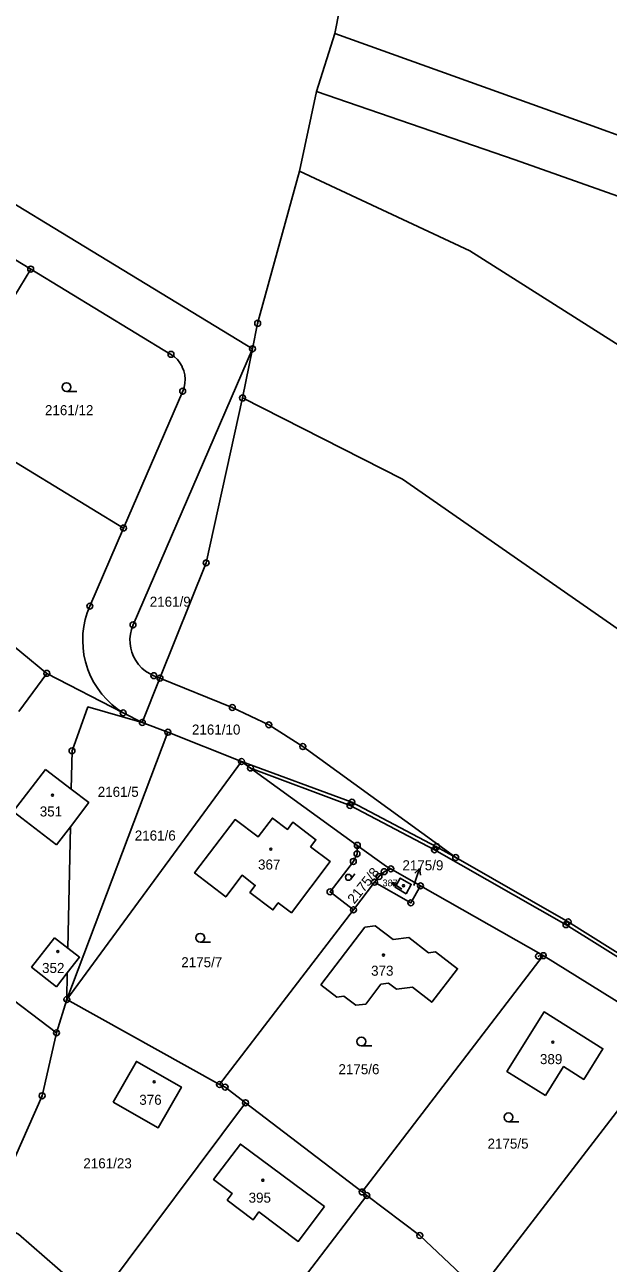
# Model space of a CAD drawing. Extents: x -725728 to -720881, y -1068679 to -1063504.
# Drawn here: x -721484.1 to -721385.1, y -1066663.8 to -1066453.8 of the extents above; entities that cross this region are included whole.
import ezdxf

# ---------------------------------------------------------------- set-up
doc = ezdxf.new("R2010")
doc.units = 0
for name, color, linetype in [('Hranice parcel', 7, 'Continuous'), ('Parcelní čísla', 7, 'Continuous'), ('Pop  PČ popisy', 7, 'Continuous'), ('Značky bodu BP', 7, 'Continuous'), ('Značky budov', 7, 'Continuous'), ('Značky kultur', 7, 'Continuous')]:
    doc.layers.add(name, color=color, linetype=linetype)

msp = doc.modelspace()

# ---------------------------------------------------------------- linework, layer by layer
at = {"layer": 'Hranice parcel'}
for p, q in [((-721434.62, -1066465.11), (-721431.52, -1066455.27)), ((-721437.52, -1066478.62), (-721434.62, -1066465.11)), ((-721500.53, -1066484.64), (-721483.09, -1066495.24)), ((-721498.34, -1066520.32), (-721483.09, -1066495.24)), ((-721483.09, -1066495.24), (-721459.3, -1066509.71)), ((-721445.47, -1066508.75), (-721465.73, -1066555.59)), ((-721447.15, -1066517.1), (-721445.47, -1066508.75)), ((-721457.31, -1066515.96), (-721467.34, -1066539.16)), ((-721453.33, -1066545.06), (-721447.15, -1066517.1)), ((-721467.34, -1066539.16), (-721498.34, -1066520.32)), ((-721467.34, -1066539.16), (-721473.07, -1066552.41)), ((-721461.16, -1066564.63), (-721453.33, -1066545.06)), ((-721499.96, -1066547.69), (-721480.36, -1066563.81)), ((-721480.36, -1066563.81), (-721485.1, -1066570.29)), ((-721480.36, -1066563.81), (-721467.4, -1066570.5)), ((-721461.16, -1066564.63), (-721464.16, -1066572.13)), ((-721462.21, -1066564.2), (-721461.16, -1066564.63)), ((-721467.4, -1066570.5), (-721464.16, -1066572.13)), ((-721464.16, -1066572.13), (-721459.81, -1066573.8)), ((-721476.97, -1066619.11), (-721459.81, -1066573.8)), ((-721459.81, -1066573.8), (-721447.33, -1066578.75)), ((-721476.97, -1066619.11), (-721447.33, -1066578.75)), ((-721445.8, -1066579.86), (-721447.33, -1066578.75)), ((-721447.33, -1066578.75), (-721428.6, -1066585.67)), ((-721427.69, -1066592.98), (-721445.8, -1066579.86)), ((-721480.57, -1066580.11), (-721476.22, -1066583.44)), ((-721428.6, -1066585.67), (-721414.24, -1066593.2)), ((-721476.35, -1066589.81), (-721478.7, -1066592.87)), ((-721476.35, -1066589.81), (-721476.79, -1066610.42)), ((-721414.24, -1066593.2), (-721411, -1066595.05)), ((-721416.97, -1066599.84), (-721422.01, -1066596.97)), ((-721424.76, -1066599.21), (-721428.35, -1066603.9)), ((-721396.15, -1066611.68), (-721416.97, -1066599.84)), ((-721508.7, -1066602.07), (-721478.72, -1066624.77)), ((-721428.35, -1066603.9), (-721451.07, -1066633.53)), ((-721479.07, -1066608.65), (-721476.79, -1066610.42)), ((-721396.15, -1066611.68), (-721426.87, -1066651.76)), ((-721373.98, -1066625.5), (-721396.15, -1066611.68)), ((-721476.88, -1066614.6), (-721478.71, -1066616.95)), ((-721476.88, -1066614.6), (-721476.97, -1066619.11)), ((-721476.97, -1066619.11), (-721478.72, -1066624.77)), ((-721451.07, -1066633.53), (-721476.97, -1066619.11)), ((-721373.98, -1066625.5), (-721407.06, -1066668.61)), ((-721471.92, -1066670.45), (-721446.66, -1066636.63)), ((-721426.87, -1066651.76), (-721446.66, -1066636.63)), ((-721452.81, -1066687.35), (-721426.08, -1066652.36)), ((-721426.08, -1066652.36), (-721426.87, -1066651.76))]:
    msp.add_line(p, q, dxfattribs=at)
for points in [[(-721431.52, -1066455.27), (-721424.48, -1066419.67), (-721421.78, -1066392.38)], [(-721592.64, -1066419.28), (-721519.06, -1066464.02), (-721445.47, -1066508.75)], [(-721230.65, -1066526.44), (-721277.41, -1066511.11), (-721331.05, -1066491.51), (-721388.47, -1066470.7), (-721431.52, -1066455.27)], [(-721434.62, -1066465.11), (-721400.9, -1066476.72), (-721289.85, -1066516.02), (-721253.91, -1066529.25), (-721228.92, -1066541.28)], [(-721445.47, -1066508.75), (-721444.6, -1066504.45), (-721437.52, -1066478.62)], [(-721437.52, -1066478.62), (-721408.58, -1066492.16), (-721301.3, -1066560.17), (-721252.76, -1066592.17), (-721191.02, -1066626.24)], [(-721459.3, -1066509.71), (-721458.72, -1066510.12), (-721458.21, -1066510.6), (-721457.77, -1066511.15), (-721457.41, -1066511.76), (-721457.37, -1066511.85), (-721457.11, -1066512.51), (-721456.96, -1066513.2), (-721456.9, -1066513.9), (-721456.94, -1066514.6), (-721457.07, -1066515.3), (-721457.31, -1066515.96)], [(-721447.15, -1066517.1), (-721420.03, -1066530.86), (-721379.52, -1066559), (-721269.58, -1066620.68), (-721222.77, -1066645.27)], [(-721473.07, -1066552.41), (-721473.5, -1066553.53), (-721473.84, -1066554.69), (-721474.08, -1066555.87), (-721474.22, -1066557.07), (-721474.26, -1066558.27), (-721474.21, -1066559.47), (-721474.05, -1066560.67), (-721473.79, -1066561.84), (-721473.74, -1066562.02), (-721473.38, -1066563.17), (-721472.92, -1066564.28), (-721472.36, -1066565.35), (-721471.72, -1066566.37), (-721471, -1066567.33), (-721470.2, -1066568.24), (-721469.33, -1066569.07), (-721468.4, -1066569.82), (-721467.4, -1066570.5)], [(-721465.73, -1066555.59), (-721466, -1066556.35), (-721466.18, -1066557.14), (-721466.26, -1066557.94), (-721466.24, -1066558.74), (-721466.12, -1066559.54), (-721465.94, -1066560.2), (-721465.65, -1066560.95), (-721465.26, -1066561.65), (-721464.78, -1066562.31), (-721464.23, -1066562.9), (-721463.61, -1066563.41), (-721462.94, -1066563.85), (-721462.21, -1066564.2)], [(-721411, -1066595.05), (-721436.92, -1066576.23), (-721442.7, -1066572.55), (-721448.89, -1066569.59), (-721461.16, -1066564.63)], [(-721464.16, -1066572.13), (-721473.37, -1066569.51), (-721476.08, -1066576.96), (-721476.22, -1066583.44)], [(-721293.92, -1066677.55), (-721362.35, -1066625.09), (-721392.29, -1066606.43), (-721414.6, -1066593.72), (-721428.93, -1066586.2), (-721445.8, -1066579.86)], [(-721478.7, -1066592.87), (-721486.07, -1066587.25), (-721480.57, -1066580.11)], [(-721476.22, -1066583.44), (-721473.23, -1066585.73), (-721476.35, -1066589.81)], [(-721435.63, -1066593.22), (-721432.27, -1066595.72), (-721438.88, -1066604.4), (-721441.09, -1066602.72), (-721442.01, -1066603.92), (-721445.91, -1066600.95), (-721445, -1066599.76), (-721447.23, -1066598.06), (-721450.01, -1066601.73), (-721455.3, -1066597.66), (-721448.42, -1066588.62), (-721444.48, -1066591.52), (-721442.08, -1066588.35), (-721439.53, -1066590.26), (-721438.63, -1066589.06), (-721434.71, -1066592.02), (-721435.63, -1066593.22)], [(-721428.35, -1066603.9), (-721432.32, -1066600.86), (-721428.36, -1066595.7), (-721427.74, -1066594.41), (-721427.69, -1066592.98)], [(-721422.01, -1066596.97), (-721422.73, -1066596.57), (-721427.69, -1066592.98)], [(-721411, -1066595.05), (-721391.94, -1066605.94), (-721362.07, -1066624.68), (-721293.39, -1066677.33)], [(-721424.76, -1066599.21), (-721424.02, -1066598.27), (-721423.13, -1066597.44), (-721422.01, -1066596.97)], [(-721419.39, -1066601.18), (-721421.29, -1066600.09), (-721420.4, -1066598.53), (-721418.53, -1066599.61), (-721419.39, -1066601.18)], [(-721416.97, -1066599.84), (-721418.6, -1066602.72), (-721424.76, -1066599.21)], [(-721433.88, -1066616.63), (-721426.39, -1066606.87), (-721424.68, -1066606.64), (-721421.63, -1066608.95), (-721418.96, -1066608.61), (-721415.6, -1066611.19), (-721414.42, -1066611.05), (-721410.69, -1066613.91), (-721415.06, -1066619.59), (-721418.35, -1066617.03), (-721421.06, -1066617.39), (-721422.42, -1066616.36), (-721423.68, -1066616.53), (-721426.27, -1066619.92), (-721427.96, -1066620.1), (-721429.95, -1066618.56), (-721431.17, -1066618.72), (-721433.88, -1066616.63)], [(-721478.71, -1066616.95), (-721482.94, -1066613.62), (-721479.07, -1066608.65)], [(-721476.79, -1066610.42), (-721474.81, -1066611.96), (-721476.88, -1066614.6)], [(-721395.76, -1066635.4), (-721402.31, -1066631.31), (-721396, -1066621.22), (-721386.02, -1066627.47), (-721389.28, -1066632.66), (-721392.71, -1066630.51), (-721395.76, -1066635.4)], [(-721478.72, -1066624.77), (-721481.16, -1066635.44), (-721490.49, -1066656.42)], [(-721469.08, -1066636.53), (-721465.15, -1066629.61), (-721457.53, -1066633.96), (-721461.46, -1066640.88), (-721469.08, -1066636.53)], [(-721446.66, -1066636.63), (-721450.11, -1066633.99), (-721451.07, -1066633.53)], [(-721433.28, -1066654.24), (-721447.51, -1066643.64), (-721452.06, -1066649.66), (-721448.9, -1066652.03), (-721449.76, -1066653.13), (-721445.34, -1066656.46), (-721444.37, -1066655.15), (-721437.7, -1066660.14), (-721433.28, -1066654.24)], [(-721407.06, -1066668.61), (-721417.1, -1066659.15), (-721426.08, -1066652.36)], [(-721490.49, -1066656.42), (-721485.18, -1066658.89), (-721471.92, -1066670.45)]]:
    msp.add_lwpolyline(points, dxfattribs=at)
at = {"layer": 'Pop  PČ popisy'}
for p, q in [((-721418.08, -1066599.76), (-721417.15, -1066596.91)), ((-721417.15, -1066596.91), (-721417.94, -1066597.7)), ((-721417.15, -1066596.91), (-721416.99, -1066598.01)), ((-721420.14, -1066600.41), (-721421.79, -1066599.26)), ((-721421.79, -1066599.26), (-721421.05, -1066599.37)), ((-721421.79, -1066599.26), (-721421.43, -1066599.92))]:
    msp.add_line(p, q, dxfattribs=at)
at = {"layer": 'Značky bodu BP'}
for centre, radius in [((-721483.09, -1066495.24), 0.5), ((-721483.09, -1066495.24), 0.0303), ((-721444.6, -1066504.45), 0.5), ((-721444.6, -1066504.45), 0.0303), ((-721445.47, -1066508.75), 0.5), ((-721459.3, -1066509.71), 0.5), ((-721459.3, -1066509.71), 0.0303), ((-721445.47, -1066508.75), 0.0303), ((-721457.31, -1066515.96), 0.5), ((-721457.31, -1066515.96), 0.0303), ((-721447.15, -1066517.1), 0.5), ((-721447.15, -1066517.1), 0.0303), ((-721467.34, -1066539.16), 0.5), ((-721467.34, -1066539.16), 0.0303), ((-721453.33, -1066545.06), 0.5), ((-721453.33, -1066545.06), 0.0303), ((-721473.07, -1066552.41), 0.5), ((-721473.07, -1066552.41), 0.0303), ((-721465.73, -1066555.59), 0.5), ((-721465.73, -1066555.59), 0.0303), ((-721480.36, -1066563.81), 0.5), ((-721480.36, -1066563.81), 0.0303), ((-721462.21, -1066564.2), 0.5), ((-721462.21, -1066564.2), 0.0303), ((-721461.16, -1066564.63), 0.5), ((-721461.16, -1066564.63), 0.0303), ((-721448.89, -1066569.59), 0.5), ((-721467.4, -1066570.5), 0.5), ((-721467.4, -1066570.5), 0.0303), ((-721448.89, -1066569.59), 0.0303), ((-721464.16, -1066572.13), 0.5), ((-721464.16, -1066572.13), 0.0303), ((-721459.81, -1066573.8), 0.5), ((-721442.7, -1066572.55), 0.5), ((-721442.7, -1066572.55), 0.0303), ((-721459.81, -1066573.8), 0.0303), ((-721476.08, -1066576.96), 0.5), ((-721476.08, -1066576.96), 0.0303), ((-721436.92, -1066576.23), 0.5), ((-721436.92, -1066576.23), 0.0303), ((-721447.33, -1066578.75), 0.5), ((-721447.33, -1066578.75), 0.0303), ((-721445.8, -1066579.86), 0.5), ((-721445.8, -1066579.86), 0.0303), ((-721428.93, -1066586.2), 0.5), ((-721428.6, -1066585.67), 0.5), ((-721428.93, -1066586.2), 0.0303), ((-721428.6, -1066585.67), 0.0303), ((-721427.69, -1066592.98), 0.5), ((-721427.74, -1066594.41), 0.5), ((-721427.74, -1066594.41), 0.0303), ((-721427.69, -1066592.98), 0.0303), ((-721414.6, -1066593.72), 0.5), ((-721414.24, -1066593.2), 0.5), ((-721414.6, -1066593.72), 0.0303), ((-721414.24, -1066593.2), 0.0303), ((-721411, -1066595.05), 0.5), ((-721428.36, -1066595.7), 0.5), ((-721428.36, -1066595.7), 0.0303), ((-721422.01, -1066596.97), 0.5), ((-721411, -1066595.05), 0.0303), ((-721424.76, -1066599.21), 0.5), ((-721424.02, -1066598.27), 0.5), ((-721424.02, -1066598.27), 0.0303), ((-721423.13, -1066597.44), 0.5), ((-721423.13, -1066597.44), 0.0303), ((-721422.01, -1066596.97), 0.0303), ((-721432.32, -1066600.86), 0.5), ((-721432.32, -1066600.86), 0.0303), ((-721424.76, -1066599.21), 0.0303), ((-721416.97, -1066599.84), 0.5), ((-721416.97, -1066599.84), 0.0303), ((-721418.6, -1066602.72), 0.5), ((-721418.6, -1066602.72), 0.0303), ((-721428.35, -1066603.9), 0.5), ((-721428.35, -1066603.9), 0.0303), ((-721392.29, -1066606.43), 0.5), ((-721391.94, -1066605.94), 0.5), ((-721392.29, -1066606.43), 0.0303), ((-721391.94, -1066605.94), 0.0303), ((-721396.96, -1066611.76), 0.5), ((-721396.15, -1066611.68), 0.5), ((-721396.96, -1066611.76), 0.0303), ((-721396.15, -1066611.68), 0.0303), ((-721476.97, -1066619.11), 0.5), ((-721476.97, -1066619.11), 0.0303), ((-721478.72, -1066624.77), 0.5), ((-721478.72, -1066624.77), 0.0303), ((-721451.07, -1066633.53), 0.5), ((-721451.07, -1066633.53), 0.0303), ((-721450.11, -1066633.99), 0.5), ((-721450.11, -1066633.99), 0.0303), ((-721481.16, -1066635.44), 0.5), ((-721481.16, -1066635.44), 0.0303), ((-721446.66, -1066636.63), 0.5), ((-721446.66, -1066636.63), 0.0303), ((-721426.87, -1066651.76), 0.5), ((-721426.87, -1066651.76), 0.0303), ((-721426.08, -1066652.36), 0.5), ((-721426.08, -1066652.36), 0.0303), ((-721417.1, -1066659.15), 0.5), ((-721417.1, -1066659.15), 0.0303)]:
    msp.add_circle(centre, radius, dxfattribs=at)
at = {"layer": 'Značky budov'}
for centre in [(-721479.39, -1066584.45), (-721442.37, -1066593.61), (-721419.86, -1066599.82), (-721478.5, -1066610.99), (-721423.26, -1066611.58), (-721394.54, -1066626.37), (-721462.13, -1066633.07), (-721443.71, -1066649.78)]:
    msp.add_circle(centre, 0.175, dxfattribs=at)
at = {"layer": 'Značky kultur'}
for p, q in [((-721477.01, -1066516.01), (-721475.26, -1066516.01)), ((-721428.81, -1066598.71), (-721428.09, -1066597.78)), ((-721454.33, -1066609.4), (-721452.58, -1066609.4)), ((-721427, -1066627), (-721425.25, -1066627)), ((-721402.04, -1066639.85), (-721400.29, -1066639.85))]:
    msp.add_line(p, q, dxfattribs=at)
for centre, radius in [((-721477.01, -1066515.26), 0.75), ((-721429.2, -1066598.4), 0.502), ((-721454.33, -1066608.65), 0.75), ((-721427, -1066626.25), 0.75), ((-721402.04, -1066639.1), 0.75)]:
    msp.add_circle(centre, radius, dxfattribs=at)

# ---------------------------------------------------------------- texts
at = {"layer": 'Parcelní čísla'}
for s, p in [('2161/12', (-721480.67, -1066520.02)), ('2161/9', (-721462.9, -1066552.5)), ('2161/10', (-721455.74, -1066574.19)), ('2161/5', (-721471.72, -1066584.75)), ('351', (-721481.55, -1066588.08)), ('2161/6', (-721465.44, -1066592.16)), ('367', (-721444.53, -1066597.08)), ('2175/9', (-721420.04, -1066597.2)), ('352', (-721481.16, -1066614.62)), ('2175/7', (-721457.55, -1066613.65)), ('373', (-721425.35, -1066615.09)), ('2175/6', (-721430.89, -1066631.79)), ('389', (-721396.71, -1066630.08)), ('376', (-721464.67, -1066636.98)), ('2175/5', (-721405.6, -1066644.41)), ('2161/23', (-721474.16, -1066647.75)), ('395', (-721446.13, -1066653.58))]:
    msp.add_text(s, height=1.7, dxfattribs=at).set_placement(p)
for s, height, rotation, p in [('2175/8', 1.7, 51, (-721428.2, -1066603.02)), ('387', 1.139, 359, (-721423.41, -1066599.9))]:
    msp.add_text(s, height=height, rotation=rotation, dxfattribs=at).set_placement(p)

doc.saveas('drawing.dxf')
